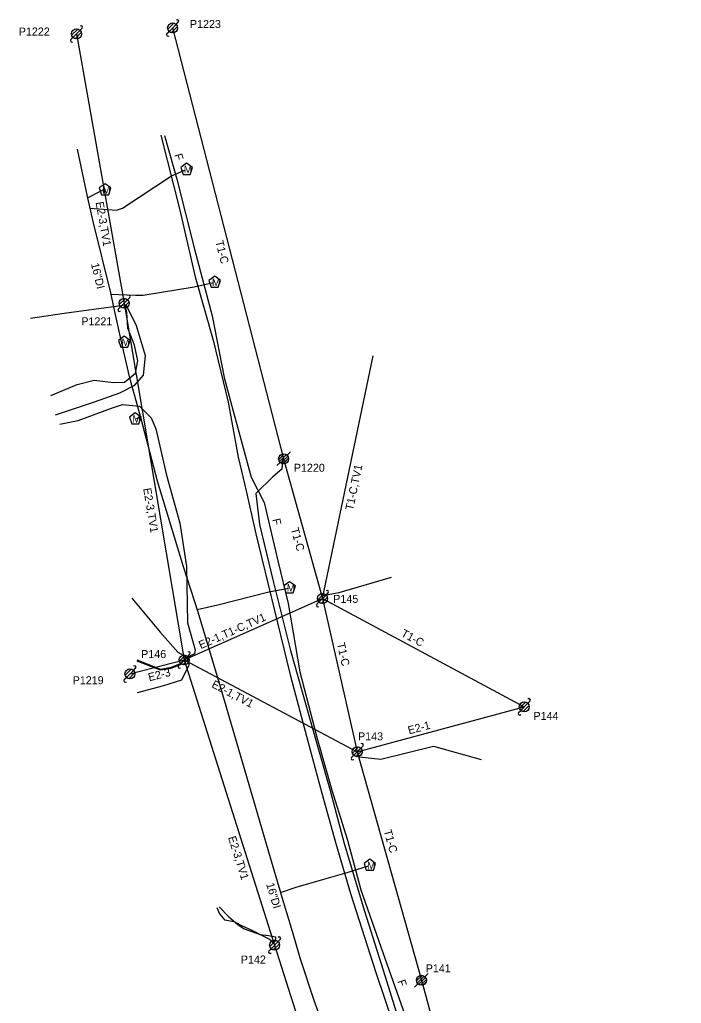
# Model space of a CAD drawing. Extents: x 1741604 to 1825760, y 1164229 to 1194908.
# Drawn here: x 1754809.2 to 1755139.7, y 1170914.1 to 1171405.6 of the extents above; entities that cross this region are included whole.
import ezdxf

# ---------------------------------------------------------------- set-up
doc = ezdxf.new("R2010")
doc.units = 0
for name, color, linetype in [('RD_EX_SU_Elec', 7, 'Continuous'), ('RD_EX_SU_H2O', 7, 'Continuous'), ('RD_EX_SU_Ovhd', 7, 'Continuous'), ('RD_EX_SU_Pole', 7, 'Continuous'), ('RD_EX_SU_Telecom', 7, 'Continuous'), ('RD_EX_SU_TX_H2O', 7, 'Continuous'), ('RD_EX_SU_TX_Pole', 7, 'Continuous'), ('RD_EX_SU_TX_Telecom', 7, 'Continuous')]:
    doc.layers.add(name, color=color, linetype=linetype)

# ---------------------------------------------------------------- blocks, each defined once
blk = doc.blocks.new('SUE_PP')
at = {"layer": 'RD_EX_SU_Pole'}
for p, q in [((-2.41, -0.65), (0.65, 2.41)), ((-1.77, -1.77), (1.77, 1.77)), ((-0.65, -2.41), (2.41, 0.65)), ((1.77, 1.77), (2.83, 2.83)), ((-2.83, -2.83), (-1.77, -1.77))]:
    blk.add_line(p, q, dxfattribs=at)
blk.add_circle((0, 0), 2.5, dxfattribs=at)
for centre, start, end in [((2.3, 3.36), 315, 135), ((-2.3, -3.36), 135, 315)]:
    blk.add_arc(centre, 0.75, start, end, dxfattribs=at)
blk = doc.blocks.new('SUE_PTP')
at = {"layer": 'RD_EX_SU_Pole'}
for p, q in [((-2.48, -0.33), (0.33, 2.48)), ((-2.1, -1.36), (1.36, 2.1)), ((-1.4, -2.08), (2.08, 1.4)), ((-0.38, -2.47), (2.47, 0.38)), ((1.77, 1.77), (3.42, 3.42)), ((-3.42, -3.42), (-1.77, -1.77)), ((1.52, -1.99), (1.99, -1.52))]:
    blk.add_line(p, q, dxfattribs=at)
blk.add_circle((0, 0), 2.5, dxfattribs=at)
blk = doc.blocks.new('SUE_WM')
at = {"layer": 'RD_EX_SU_H2O'}
blk.add_lwpolyline([(0, 3.05), (-2.9, 0.94), (-1.79, -2.47), (1.79, -2.47), (2.9, 0.94)], close=True, dxfattribs=at)
blk.add_text('M', height=3.75, dxfattribs=at).set_placement((-1.43, -1.88))

msp = doc.modelspace()

# ---------------------------------------------------------------- linework, layer by layer
at = {"layer": 'RD_EX_SU_Elec'}
for points in [[(1754814.62, 1171256.51), (1754831.33, 1171259.01), (1754861.05, 1171262.93)], [(1754960.42, 1171117.89), (1754968.7, 1171119.37), (1754994.89, 1171127.08)], [(1754868.01, 1171069.37), (1754881.19, 1171072.98), (1754890.11, 1171075.67), (1754893.91, 1171083.3), (1754893.57, 1171085.77), (1754892.08, 1171086.94)], [(1754907.65, 1170962.05), (1754909.03, 1170958.87), (1754911.55, 1170955.81), (1754916.3, 1170955), (1754919.99, 1170952.99), (1754925.54, 1170950.47), (1754930.96, 1170947.68), (1754933.94, 1170946.18), (1754935.59, 1170944.79), (1754935.68, 1170944.37)]]:
    msp.add_lwpolyline(points, dxfattribs=at)
at = {"layer": 'RD_EX_SU_H2O'}
for p, q in [((1754860.91, 1171244.2), (1754859.95, 1171244.12)), ((1754869.49, 1171206.78), (1754867.39, 1171206.23))]:
    msp.add_line(p, q, dxfattribs=at)
for points in [[(1754837.83, 1171340.85), (1754842.95, 1171317.29), (1754845.76, 1171304.78), (1754854.47, 1171269.1), (1754856.76, 1171258.96), (1754860.29, 1171242.54), (1754863.9, 1171227.35), (1754869.61, 1171206.32), (1754877.84, 1171175.17), (1754890.76, 1171132.46), (1754898.12, 1171109.8), (1754909.27, 1171072.45), (1754923.63, 1171023.45), (1754934.25, 1170986.91)], [(1754844.26, 1171311.49), (1754857.48, 1171310.52), (1754860.58, 1171311.4), (1754885.03, 1171327.66), (1754892.08, 1171330.65)], [(1754843.12, 1171316.54), (1754850.22, 1171320.21), (1754851.14, 1171320.93)], [(1754854.61, 1171268.45), (1754866.97, 1171267.96), (1754870.84, 1171267.89), (1754896.27, 1171272.13), (1754906.02, 1171274.27)], [(1754897.79, 1171110.83), (1754908.21, 1171113.3), (1754933.69, 1171119.72), (1754943.39, 1171121.54)], [(1754934.25, 1170986.91), (1754939.08, 1170970.59), (1754939.58, 1170968.79), (1754945.29, 1170950.08), (1754949.33, 1170936.37), (1754956.06, 1170915.61), (1754962.38, 1170897.97)], [(1754939.41, 1170969.42), (1754947.35, 1170972.16), (1754961.12, 1170976.2), (1754972.8, 1170979.42), (1754983.48, 1170982.82)]]:
    msp.add_lwpolyline(points, dxfattribs=at)
msp.add_lwpolyline([(1754984.08, 1170986.14), (1754981.18, 1170984.04), (1754982.29, 1170980.63), (1754985.87, 1170980.63), (1754986.98, 1170984.04)], close=True, dxfattribs=at)
at = {"layer": 'RD_EX_SU_Ovhd'}
for p, q in [((1754885.57, 1171401.52), (1754941.04, 1171186.19)), ((1754837.54, 1171398.5), (1754861.33, 1171263.9)), ((1754861.33, 1171263.9), (1754891.36, 1171085.68)), ((1754960.45, 1171116.34), (1754985.68, 1171237.62)), ((1754941.04, 1171186.19), (1754960.45, 1171116.34)), ((1754891.36, 1171085.68), (1754960.45, 1171116.34)), ((1754960.45, 1171116.34), (1755061.26, 1171062.26)), ((1754960.45, 1171116.34), (1754977.8, 1171039.83)), ((1754864.27, 1171078.7), (1754891.36, 1171085.68)), ((1754891.36, 1171085.68), (1754977.8, 1171039.83)), ((1754891.36, 1171085.68), (1754936.53, 1170943.16)), ((1754977.8, 1171039.83), (1755061.26, 1171062.26)), ((1754977.8, 1171039.83), (1755009.84, 1170925.6)), ((1754936.53, 1170943.16), (1754975.2, 1170821.28)), ((1755009.84, 1170925.6), (1755050.22, 1170776.56))]:
    msp.add_line(p, q, dxfattribs=at)
at = {"layer": 'RD_EX_SU_Pole'}
for p, q in [((1754887.33, 1171403.29), (1754888.4, 1171404.35)), ((1754835.12, 1171397.85), (1754838.18, 1171400.91)), ((1754835.77, 1171396.73), (1754839.3, 1171400.26)), ((1754839.3, 1171400.26), (1754840.37, 1171401.32)), ((1754882.74, 1171398.69), (1754883.8, 1171399.75)), ((1754883.15, 1171400.87), (1754886.21, 1171403.94)), ((1754883.8, 1171399.75), (1754887.33, 1171403.29)), ((1754884.92, 1171399.11), (1754887.98, 1171402.17)), ((1754834.71, 1171395.67), (1754835.77, 1171396.73)), ((1754836.89, 1171396.08), (1754839.95, 1171399.14)), ((1754861.85, 1171078.05), (1754864.92, 1171081.11)), ((1754862.5, 1171076.93), (1754866.04, 1171080.46)), ((1754866.04, 1171080.46), (1754867.1, 1171081.52)), ((1754861.44, 1171075.87), (1754862.5, 1171076.93)), ((1754863.62, 1171076.28), (1754866.68, 1171079.34))]:
    msp.add_line(p, q, dxfattribs=at)
for centre in [(1754837.54, 1171398.5), (1754885.57, 1171401.52), (1754864.27, 1171078.7)]:
    msp.add_circle(centre, 2.5, dxfattribs=at)
for centre, start, end in [((1754887.87, 1171404.88), 315, 135), ((1754839.84, 1171401.85), 315, 135), ((1754835.24, 1171395.14), 135, 315), ((1754883.27, 1171398.16), 135, 315), ((1754866.57, 1171082.05), 315, 135), ((1754861.97, 1171075.34), 135, 315)]:
    msp.add_arc(centre, 0.75, start, end, dxfattribs=at)
at = {"layer": 'RD_EX_SU_Telecom'}
for points in [[(1754879.71, 1171347.96), (1754889.12, 1171310.39), (1754896.79, 1171277.14), (1754905.82, 1171245.51), (1754913.32, 1171214.53), (1754918.38, 1171186.95), (1754922.37, 1171170.13), (1754927.14, 1171148.68), (1754936.24, 1171111.1), (1754944.28, 1171078.23), (1754953.07, 1171045.18), (1754960.14, 1171019.1), (1754967.13, 1170994.05)], [(1754881.58, 1171347.68), (1754887.75, 1171325.88), (1754896.48, 1171291.03), (1754905.4, 1171257.6), (1754911.28, 1171226.85), (1754915.1, 1171212.58), (1754924.74, 1171177.07), (1754931.28, 1171164.35), (1754938.12, 1171135.17), (1754943.3, 1171113.9), (1754949.2, 1171079.68), (1754957.84, 1171046.43), (1754965.05, 1171020.68), (1754972.97, 1170995.6)], [(1754824.68, 1171217.83), (1754837.87, 1171223.34), (1754846.38, 1171225.57), (1754856.01, 1171224.34), (1754861.54, 1171224.44), (1754867.04, 1171228.97), (1754868.25, 1171235.16), (1754866.5, 1171242.94), (1754863.26, 1171251.44), (1754862.63, 1171259.26), (1754862.02, 1171262.42)], [(1754827.11, 1171208.23), (1754846.58, 1171214.64), (1754859.25, 1171219.18), (1754866.73, 1171222.93), (1754870.99, 1171227.93), (1754871.96, 1171237.66), (1754867.55, 1171252.56), (1754862.48, 1171262.72)], [(1754829.17, 1171203.5), (1754838.31, 1171205.42), (1754855.08, 1171211.48), (1754860.48, 1171213.33), (1754869.07, 1171212.54), (1754874.85, 1171206.68), (1754877.22, 1171201.12), (1754882.47, 1171177.99), (1754889.24, 1171153.96), (1754892.49, 1171132.35), (1754892.98, 1171104.28), (1754896.85, 1171090.71), (1754896.5, 1171088.81), (1754891.98, 1171086.49)], [(1754940.55, 1171186.59), (1754940.16, 1171181), (1754935.58, 1171177.12), (1754927.09, 1171168.93), (1754928.99, 1171153.45), (1754935.97, 1171124.46), (1754944.53, 1171090.46), (1754953.94, 1171056.74), (1754964.19, 1171020.46), (1754971.23, 1170994.02)], [(1754865.23, 1171116.5), (1754879.35, 1171099.52), (1754888.17, 1171089.64), (1754892.07, 1171087.35), (1754891.83, 1171086.35)], [(1754867.66, 1171085.27), (1754879.39, 1171080.68), (1754884.84, 1171081.53), (1754889.43, 1171083.46), (1754891.42, 1171085.36)], [(1754867.76, 1171085.74), (1754879.49, 1171081.15), (1754884.94, 1171082), (1754889.53, 1171083.92), (1754891.52, 1171085.83)], [(1754977.98, 1171039.48), (1754978.7, 1171037.21), (1754989.54, 1171036.09), (1755015.81, 1171042.54), (1755039.66, 1171035.91)], [(1754967.13, 1170994.05), (1754974.43, 1170968.95), (1754987.04, 1170929.46), (1755004.13, 1170879.16), (1755015.94, 1170845.8), (1755027.84, 1170815.17), (1755036.74, 1170794.1), (1755046.9, 1170772.73), (1755058.13, 1170753.54), (1755068.96, 1170735.75), (1755072.88, 1170726.57), (1755079.23, 1170717.91), (1755082.2, 1170712.4), (1755082.99, 1170707.43), (1755087.24, 1170669.18), (1755089.17, 1170658.27), (1755093.84, 1170646.29), (1755105.7, 1170595.36), (1755111, 1170568.73), (1755116.38, 1170542.14), (1755124.51, 1170504.65), (1755130.68, 1170470.03), (1755139.68, 1170422.81)], [(1754971.23, 1170994.02), (1754981.43, 1170960.16), (1754990.73, 1170930.67), (1754998.66, 1170905.01)], [(1754972.97, 1170995.6), (1754979.53, 1170970.89), (1754989.66, 1170942.34), (1755001.61, 1170908.39)], [(1754908.85, 1170962.24), (1754913.59, 1170957.33), (1754918.21, 1170953.41), (1754921.37, 1170951.31), (1754924.63, 1170950.13), (1754929.24, 1170948.56), (1754933.42, 1170948), (1754936.99, 1170947.34), (1754937.02, 1170946.12), (1754935.53, 1170944.22)]]:
    msp.add_lwpolyline(points, dxfattribs=at)

# ---------------------------------------------------------------- block references
at = {"layer": 'RD_EX_SU_H2O'}
for p in [(1754892.57, 1171330.81), (1754851.85, 1171320.59), (1754906.61, 1171274.42), (1754861.45, 1171244.38), (1754866.92, 1171206.1), (1754943.99, 1171121.75)]:
    msp.add_blockref('SUE_WM', p, dxfattribs=at)
at = {"layer": 'RD_EX_SU_Pole'}
for p in [(1754861.33, 1171263.9), (1754960.45, 1171116.34), (1754891.36, 1171085.68), (1755061.26, 1171062.26), (1754977.8, 1171039.83), (1754936.53, 1170943.16)]:
    msp.add_blockref('SUE_PP', p, dxfattribs=at)
at = {"layer": 'RD_EX_SU_Telecom'}
for p in [(1754941.04, 1171186.19), (1755009.84, 1170925.6)]:
    msp.add_blockref('SUE_PTP', p, dxfattribs=at)

# ---------------------------------------------------------------- texts
at = {"layer": 'RD_EX_SU_H2O'}
msp.add_text('M', height=3.75, dxfattribs=at).set_placement((1754982.71, 1170981.1))
at = {"layer": 'RD_EX_SU_Ovhd'}
for s, rotation, p in [('E2-3,TV1', 280.0262, (1754847.08, 1171314.34)), ('T1-C', 284.447, (1754906.87, 1171294.78)), ('T1-C,TV1', 78.2508, (1754975.7, 1171160.22)), ('E2-3,TV1', 279.564, (1754870.85, 1171171.28)), ('T1-C', 285.5265, (1754944.55, 1171151.15)), ('E2-1,T1-C,TV1', 23.9286, (1754899.67, 1171091.05)), ('T1-C', 331.7896, (1754999.31, 1171097.76)), ('T1-C', 282.7736, (1754967.59, 1171093.87)), ('E2-3', 14.453, (1754873.91, 1171074.98)), ('E2-1,TV1', 332.0539, (1754904.69, 1171072.27)), ('E2-1', 15.0455, (1755003.7, 1171048.46)), ('T1-C', 285.6727, (1754990.95, 1171000.34)), ('E2-3,TV1', 287.5859, (1754913.19, 1170996.96))]:
    msp.add_text(s, height=4, rotation=rotation, dxfattribs=at).set_placement(p)
at = {"layer": 'RD_EX_SU_TX_H2O'}
for rotation, p in [(283.7041, (1754844.76, 1171283.56)), (286.6943, (1754932.24, 1170973.7))]:
    msp.add_text('16"DI', height=4, rotation=rotation, dxfattribs=at).set_placement(p)
at = {"layer": 'RD_EX_SU_TX_Pole'}
for s, p in [('P1223', (1754894.22, 1171401.46)), ('P1222', (1754808.73, 1171397.71)), ('P1221', (1754839.96, 1171252.91)), ('P1220', (1754946.13, 1171179.73)), ('P145', (1754965.83, 1171114.21)), ('P146', (1754869.85, 1171086.63)), ('P1219', (1754835.65, 1171073.56)), ('P144', (1755065.82, 1171055.7)), ('P143', (1754978.19, 1171045.51)), ('P142', (1754919.65, 1170933.99)), ('P141', (1755012, 1170929.58))]:
    msp.add_text(s, height=4, dxfattribs=at).set_placement(p)
at = {"layer": 'RD_EX_SU_TX_Telecom'}
for rotation, p in [(285.8061, (1754886.36, 1171338.11)), (283.1839, (1754935.32, 1171155.9)), (289.3952, (1754997.84, 1170925.14))]:
    msp.add_text('F', height=4, rotation=rotation, dxfattribs=at).set_placement(p)

doc.saveas('drawing.dxf')
